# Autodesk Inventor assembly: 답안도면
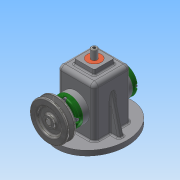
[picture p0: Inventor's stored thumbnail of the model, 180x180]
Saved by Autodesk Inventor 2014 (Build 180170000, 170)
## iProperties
Created: 2017-07
Part Number: 답안도면
Document SubType Name: Assembly
Designer: user
Author: user
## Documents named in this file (16)
- C:\Users\user\Desktop\470707V1014\답안도면.iam
- C:\Users\user\Desktop\470707V1014\V벨트풀리.ipt
- C:\Users\user\Desktop\470707V1014\고정핀 1.2 x  8.ipt
- C:\Users\user\Desktop\470707V1014\뒤커버.ipt
- C:\Users\user\Desktop\470707V1014\링크.ipt
- C:\Users\user\Desktop\470707V1014\멈춤나사 M3x8.ipt
- C:\Users\user\Desktop\470707V1014\베어링 12 x 32 x 10.ipt
- C:\Users\user\Desktop\470707V1014\볼트 M4 x 12.ipt
- C:\Users\user\Desktop\470707V1014\부시.ipt
- C:\Users\user\Desktop\470707V1014\슬라이드.ipt
- C:\Users\user\Desktop\470707V1014\앞커버.ipt
- C:\Users\user\Desktop\470707V1014\오일실 12 25 7.ipt
- C:\Users\user\Desktop\470707V1014\키 4 x 4 x 10.ipt
- C:\Users\user\Desktop\470707V1014\편심축.ipt
- C:\Users\user\Desktop\470707V1014\핀 5 x 18.ipt
- C:\Users\user\Desktop\470707V1014\본체.ipt
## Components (3 placed, 3 different names)
1. V벨트풀리:1 — Mate:5, Angle:2, Mate:7
2. 고정핀 1.2 x  8:1 — Mate:12, Mate:13
3. 핀 5 x 18:1 — Insert:10, Mate:12
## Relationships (6: Mate 4, Angle 1, Insert 1)
- Mate:5: V벨트풀리:1
- Angle:2: V벨트풀리:1
- Mate:7: V벨트풀리:1
- Insert:10: 핀 5 x 18:1
- Mate:12: 고정핀 1.2 x  8:1 ↔ 핀 5 x 18:1
- Mate:13: 고정핀 1.2 x  8:1
